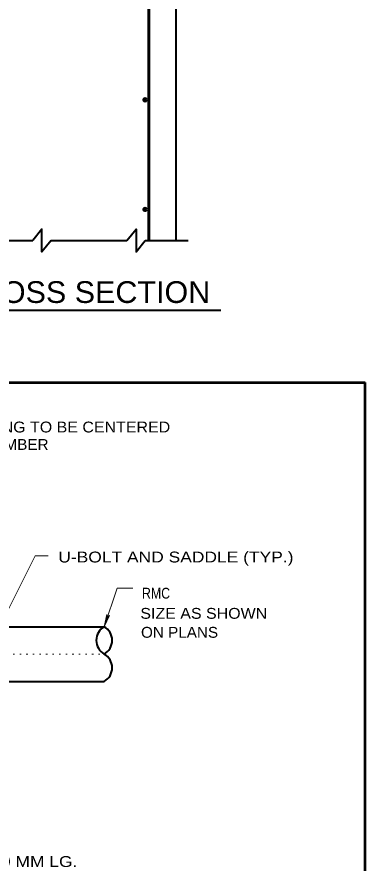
# Model space of a CAD drawing. Extents: x 312583 to 312854, y 144419 to 144597.
# Drawn here: x 312761.7 to 312786.1, y 144448.4 to 144507.6 of the extents above; entities that cross this region are included whole.
import ezdxf
from ezdxf.enums import TextEntityAlignment as Align

# ---------------------------------------------------------------- set-up
doc = ezdxf.new("R2010")
doc.units = 0
doc.header["$LTSCALE"] = 0.3
doc.linetypes.add('DOTTED', pattern=[1.5, 0.3, -1.2])
doc.layers.add('1', color=7, linetype='Continuous', lineweight=13)

msp = doc.modelspace()

# ---------------------------------------------------------------- linework, layer by layer
at = {"layer": '1', "lineweight": 40}
for p, q in [((312772.8288, 144491.9488), (312772.8288, 144521.6571)), ((312758.1012, 144491.9488), (312762.7855, 144491.9488)), ((312764.0658, 144491.9488), (312769.3788, 144491.9488)), ((312770.6592, 144491.9488), (312773.6722, 144491.9488)), ((312757.0815, 144487.0651), (312775.9415, 144487.0651)), ((312760.9189, 144464.9318), (312767.7882, 144464.9318)), ((312760.7196, 144461.0985), (312767.7882, 144461.0985))]:
    msp.add_line(p, q, dxfattribs=at)
at = {"layer": '1', "lineweight": 60}
msp.add_line((312770.9122, 144491.9488), (312770.9122, 144516.2291), dxfattribs=at)
at = {"layer": '1', "lineweight": 53}
for p in [(312708.3804, 144482.0146), (312786.0518, 144423.0846)]:
    msp.add_line(p, (312786.0518, 144482.0146), dxfattribs=at)
at = {"layer": '1'}
for p, q in [((312762.9429, 144469.8845), (312760.7196, 144465.4071)), ((312763.8552, 144469.8845), (312762.9429, 144469.8845)), ((312767.7882, 144464.9318), (312767.9646, 144465.7905)), ((312767.7882, 144464.9318), (312768.1639, 144465.7215)), ((312767.9646, 144465.7905), (312767.9799, 144465.4915)), ((312768.1639, 144465.7215), (312767.9799, 144465.4915))]:
    msp.add_line(p, q, dxfattribs=at)
at = {"layer": '1', "linetype": 'DOTTED'}
msp.add_line((312725.9896, 144463.0151), (312767.7882, 144463.0151), dxfattribs=at)
at = {"layer": '1', "lineweight": 40}
for points in [[(312764.0658, 144491.9488), (312763.4295, 144491.1514), (312763.4295, 144492.7461), (312762.7855, 144491.9488)], [(312769.3788, 144491.9488), (312770.0152, 144492.7461), (312770.0152, 144491.1514), (312770.6592, 144491.9488)]]:
    msp.add_lwpolyline(points, dxfattribs=at)
at = {"layer": '1'}
msp.add_lwpolyline([(312769.7892, 144467.6151), (312768.6929, 144467.6151), (312767.7882, 144464.9318)], dxfattribs=at)
at = {"layer": '1', "lineweight": 60}
for centre, radius in [((312770.6445, 144501.7902), 0.085), ((312770.6445, 144501.7902), 0.051), ((312770.6445, 144501.7902), 0.0135), ((312770.6445, 144494.1235), 0.085), ((312770.6445, 144494.1235), 0.051), ((312770.6445, 144494.1235), 0.0135)]:
    msp.add_circle(centre, radius, dxfattribs=at)
at = {"layer": '1', "lineweight": 40}
for centre, start, end in [((312768.3281, 144463.9735), 119.39202, 240.60798), ((312767.2484, 144463.9735), 299.39202, 60.60798), ((312767.2484, 144462.0568), 299.39202, 60.60798)]:
    msp.add_arc(centre, 1.0999, start, end, dxfattribs=at)

# ---------------------------------------------------------------- texts
at = {"layer": '1', "width": 1.05}
msp.add_text('CROSS SECTION', height=1.52, dxfattribs=at).set_placement((312766.3749, 144487.5789), align=Align.CENTER)
at = {"layer": '1'}
for s, width, p in [('BUSHING TO BE CENTERED', 1.1, (312757.191, 144478.5182)), ('IN CHAMBER', 1.05, (312757.191, 144477.2982)), ('U-BOLT AND SADDLE (TYP.)', 1.2, (312764.5719, 144469.4235)), ('RMC', 0.85, (312770.4332, 144466.8935)), ('SIZE AS SHOWN', 1.1, (312770.3182, 144465.4828)), ('ON PLANS', 1.05, (312770.3642, 144464.1565)), ('TINNED COPPER BRAID,  610 MM LG.', 1.2, (312744.0903, 144448.1198))]:
    msp.add_text(s, height=0.76, dxfattribs=dict(at, width=width)).set_placement(p)

doc.saveas('drawing.dxf')
